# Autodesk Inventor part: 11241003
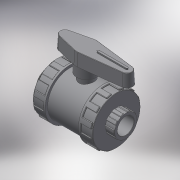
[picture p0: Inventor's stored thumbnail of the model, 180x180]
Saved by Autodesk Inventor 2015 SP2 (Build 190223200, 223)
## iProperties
Created: 2017-11
Part Number: 11241003
Material: Generic
Description: PLASSON BI STOP VALVE THR PVC 3/8"
Document SubType Name: Modeling
Designer: KIM
Density: 1 g/cm^3
Appearance: Default
Author: KIM
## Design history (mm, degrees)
derived "112410 - 112710.ipt"
feature "Solid1::112410 - 112710.ipt"
tag "TaggingFeature1"
body "Solid1"
other parameters: "d0" = 71, "d1" = 14.95, "d2" = 45, "d3" = 12, "d4" = 11.96, "d5" = 8.4, "d7" = 20.93, "d8" = 40.5, "d13" = 0.4485, "d23" = 12, "d24" = 43.2, "d25" = 0.299, "d26" = 0.4485, "d27" = 6.75, "d28" = 3.375, "d29" = 9, "d30" = 0, "d35" = 0.4485, "d39" = 22.5, "d45" = 360 deg, "d47" = 0.299, "d50" = 24.75, "d51" = 13.5, "d53" = 0, "d55" = 2.99, "d56" = 1.495, "d57" = 8.4, "d58" = 0, "d59" = 0.4485, "d61" = 360 deg, "d63" = 18, "d64" = 45, "d66" = 65, "d68" = 9, "d69" = 19.5, "d70" = 11.25, "d71" = 3 deg, "d73" = 0.9, "d74" = 26, "d75" = 1.35, "d76" = 0, "d77" = 0.299, "G_" = 14.95, "l_" = 12, "H_" = 71, "K_" = 45, "F_" = 45, "J_" = 65, "d67" = 18, "d72" = 4.5
